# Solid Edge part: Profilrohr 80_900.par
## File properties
Username: ahadarics
Dokumentum tartalom típus: 0
Author: ahadarics
Last saved by: ahadarics
Revision: 91
Sűrűség: 0,000 kg/m^3
Pontosság: 0,990
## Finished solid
Body 1: solid body, 147 faces, 434 edges, 288 vertices.
  Faces by surface: cylinder 85, plane 62
  Edges by curve: line 264, circle 170
Bounding box of the edges (mm): 86.600 x 86.600 x 948.000, from (-43.3, -43.3, -911.5) to (43.3, 43.3, 36.5).
Cylindrical faces by radius (mm): R0.1 x8, R0.2 x30, R0.5 x22, R1 x8, R4.6 x4, R7 x4, R40 x1, R42.7 x8
Planar faces by outward normal: +x 6, +y 6, +z 1, -x 4, -y 4, -z 1, oblique 40
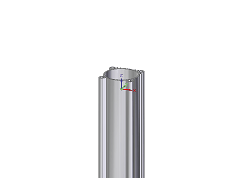
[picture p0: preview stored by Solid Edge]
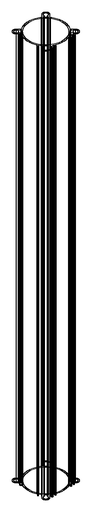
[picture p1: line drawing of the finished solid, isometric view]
